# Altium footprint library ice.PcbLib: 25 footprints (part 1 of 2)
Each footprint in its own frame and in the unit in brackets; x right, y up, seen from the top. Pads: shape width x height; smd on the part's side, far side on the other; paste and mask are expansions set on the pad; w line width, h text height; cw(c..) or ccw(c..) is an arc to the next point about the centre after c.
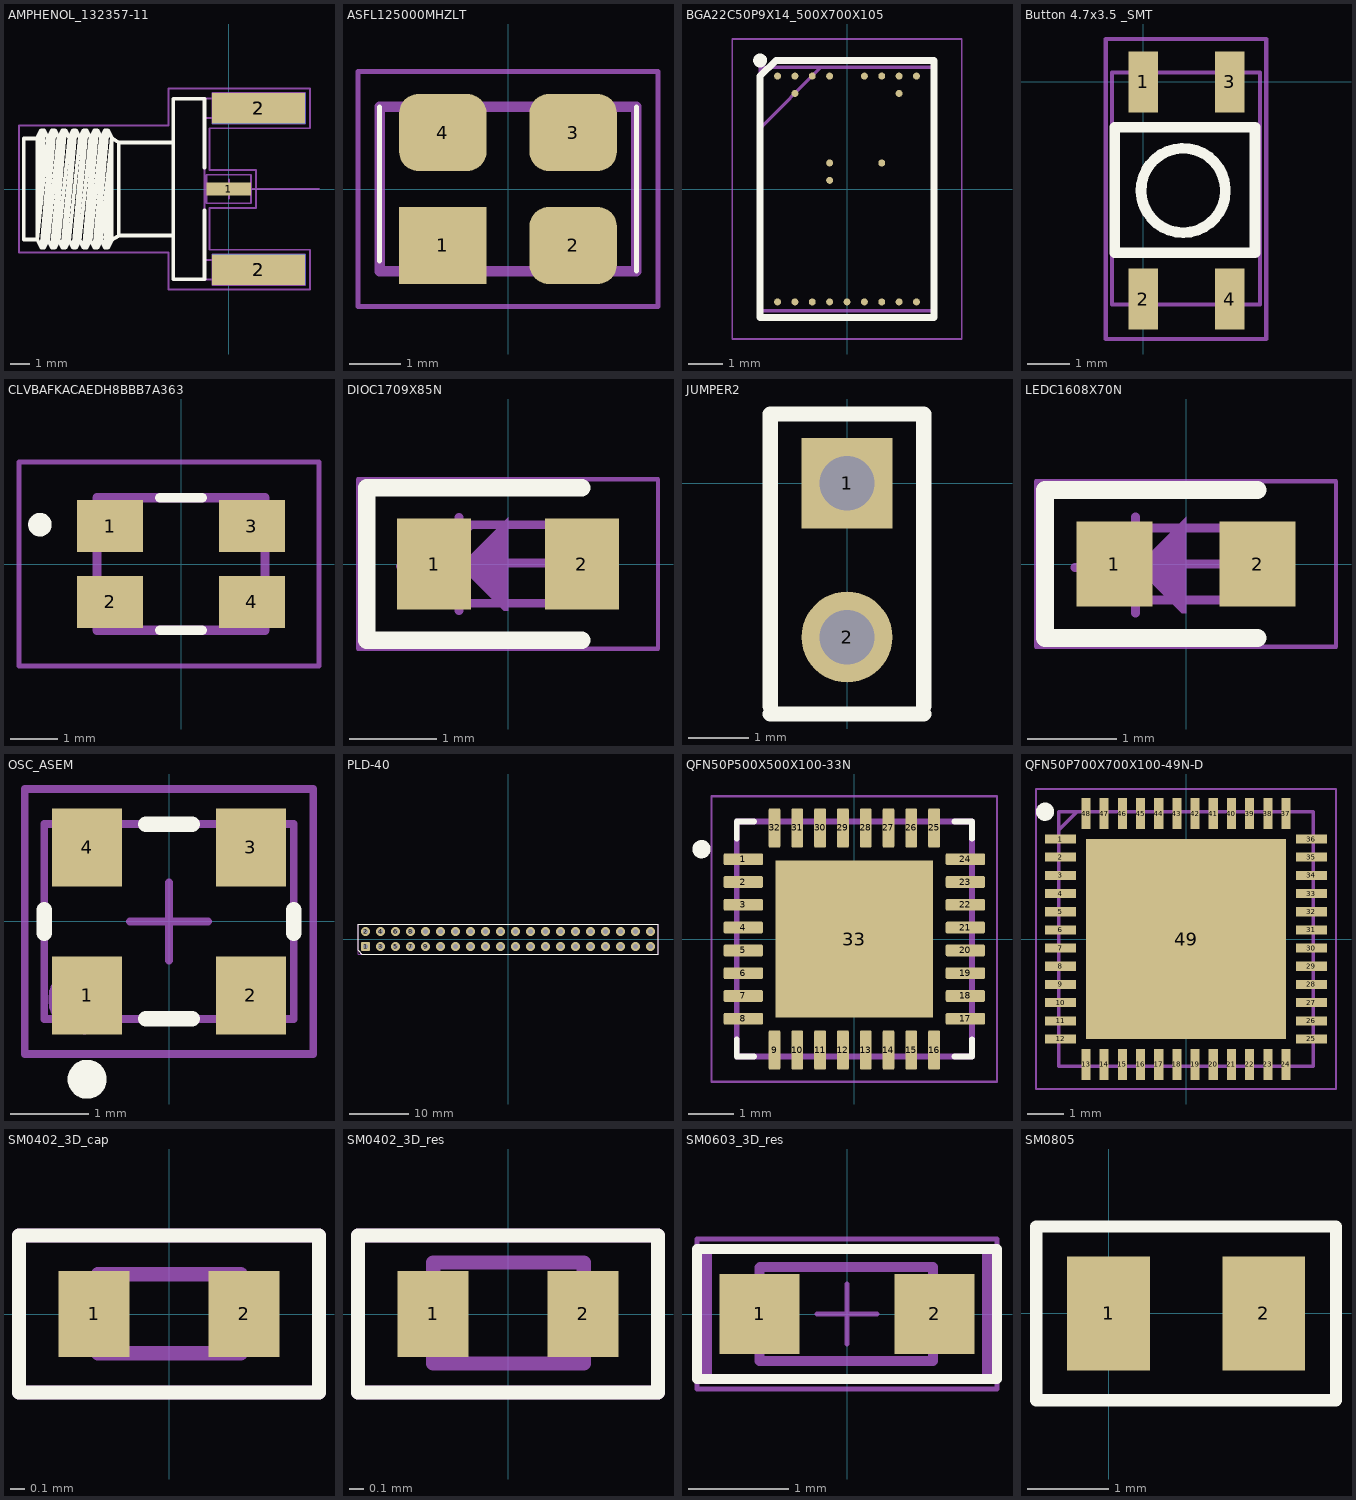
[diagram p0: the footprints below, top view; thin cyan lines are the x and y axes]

## AMPHENOL_132357-11 [mm]
height 1.2
pads (5):
  rect 2.35x0.7 smd: 1(0,0)
  rect 4.9x1.6 smd: 2(1.575,-4.25) 2(1.575,4.25)
  rect 4.9x1.6 smd far side: 2(1.575,-4.25) 2(1.575,4.25)
Top Overlay:
  lines w0.2: -10.09,2.665 -10.805,2.665 -10.805,-2.665 -10.09,-2.665 ; -6.17,-2.665 -5.795,-2.453 ; -2.925,-2.453 -5.795,-2.453 ; -2.925,2.447 -5.795,2.447 ; -1.275,-1.137 -1.275,-4.76 -2.925,-4.76 -2.925,4.76 -1.275,4.76 -1.275,1.137 ; -10.09,-2.665 -10.09,2.715 -9.879,3.094 ; -10.09,-2.665 -9.879,-3.094 ; -10.09,-2.665 -9.53,2.715 ; -10.09,-2.665 -9.741,3.094 ; -10.09,-2.665 -9.879,3.094 ; -9.879,-3.094 -9.741,-3.094 ; -9.879,-3.094 -9.319,3.094 ; -9.879,3.094 -9.741,3.094 ; -9.741,-3.094 -9.53,-2.715 ; -9.741,-3.094 -9.181,3.094 ; -9.741,3.094 -9.53,2.715 ; -9.53,-2.715 -9.319,-3.094 ; -9.53,-2.715 -8.97,2.715 ; -9.53,2.715 -9.319,3.094 ; -9.319,-3.094 -9.181,-3.094 ; -9.319,-3.094 -8.759,3.094 ; -9.319,3.094 -9.181,3.094 ; -9.181,-3.094 -8.97,-2.715 ; -9.181,-3.094 -8.621,3.094 ; -9.181,3.094 -8.97,2.715 ; -8.97,-2.715 -8.759,-3.094 ; -8.97,-2.715 -8.41,2.715 ; -8.97,2.715 -8.759,3.094 ; -8.759,-3.094 -8.621,-3.094 ; -8.759,-3.094 -8.199,3.094 ; -8.759,3.094 -8.621,3.094 ; -8.621,-3.094 -8.41,-2.715 ; -8.621,-3.094 -8.061,3.094 ; -8.621,3.094 -8.41,2.715 ; -8.41,-2.715 -8.199,-3.094 ; -8.41,-2.715 -7.85,2.715 ; -8.41,2.715 -8.199,3.094 ; -8.199,-3.094 -8.061,-3.094 ; -8.199,-3.094 -7.639,3.094 ; -8.199,3.094 -8.061,3.094 ; -8.061,-3.094 -7.85,-2.715 ; -8.061,-3.094 -7.501,3.094 ; -8.061,3.094 -7.85,2.715 ; -7.85,-2.715 -7.639,-3.094 ; -7.85,-2.715 -7.29,2.715 ; -7.85,2.715 -7.639,3.094 ; -7.639,-3.094 -7.501,-3.094 ; -7.639,-3.094 -7.079,3.094 ; -7.639,3.094 -7.501,3.094 ; -7.501,-3.094 -7.29,-2.715 ; -7.501,-3.094 -6.941,3.094 ; -7.501,3.094 -7.29,2.715 ; -7.29,-2.715 -7.079,-3.094 ; -7.29,-2.715 -6.73,2.715 ; -7.29,2.715 -7.079,3.094 ; -7.079,-3.094 -6.941,-3.094 ; -7.079,-3.094 -6.519,3.094 ; -7.079,3.094 -6.941,3.094 ; -6.941,-3.094 -6.73,-2.715 ; -6.941,-3.094 -6.381,3.094 ; -6.941,3.094 -6.73,2.715 ; -6.73,-2.715 -6.519,-3.094 ; -6.73,-2.715 -6.17,2.713 ; -6.73,2.715 -6.519,3.094 ; -6.519,-3.094 -6.381,-3.094 ; -6.519,-3.094 -6.17,2.713 ; -6.519,3.094 -6.381,3.094 ; -6.381,-3.094 -6.17,-2.715 -6.17,2.713 ; -6.381,-3.094 -6.17,2.665 -5.795,2.447 ; -6.381,3.094 -6.17,2.713 ; -5.795,-2.453 -5.795,2.447
Mechanical 8:
  lines w0.1: -0.5,0 0,0 ; 0,-0.5 0,0 ; 0,0.5 0,0 ; 0.5,0 0,0 ; 1.075,-4.25 1.575,-4.25 ; 1.075,4.25 1.575,4.25 ; 1.575,-4.75 1.575,-4.25 ; 1.575,-3.75 1.575,-4.25 ; 1.575,3.75 1.575,4.25 ; 1.575,4.75 1.575,4.25 ; 2.075,-4.25 1.575,-4.25 ; 2.075,4.25 1.575,4.25 ; -1.175,-0.75 -1.175,0.75 1.175,0.75 1.175,-0.75 -1.175,-0.75 ; -0.875,-5.05 4.025,-5.05 4.025,-3.45 -0.875,-3.45 -0.875,-5.05 ; -0.875,3.45 4.025,3.45 4.025,5.05 -0.875,5.05 -0.875,3.45
Mechanical 14:
  lines w0.1: -10.09,2.665 -10.805,2.665 -10.805,-2.665 -10.09,-2.665 ; -6.17,-2.665 -5.795,-2.453 ; -2.925,-2.453 -5.795,-2.453 ; -2.925,2.447 -5.795,2.447 ; -1.275,-4.76 -1.275,0 ; -1.275,-3.74 3.475,-3.74 3.475,-4.76 -2.925,-4.76 -2.925,4.76 3.475,4.76 3.475,3.74 -1.275,3.74 ; -1.275,-0.251 0.635,-0.251 0.635,0.251 -1.275,0.251 ; -1.275,4.76 -1.275,0 ; 4.75,0 -1.275,0 ; -10.09,-2.665 -10.09,2.715 -9.879,3.094 ; -10.09,-2.665 -9.879,-3.094 ; -10.09,-2.665 -9.53,2.715 ; -10.09,-2.665 -9.741,3.094 ; -10.09,-2.665 -9.879,3.094 ; -9.879,-3.094 -9.741,-3.094 ; -9.879,-3.094 -9.319,3.094 ; -9.879,3.094 -9.741,3.094 ; -9.741,-3.094 -9.53,-2.715 ; -9.741,-3.094 -9.181,3.094 ; -9.741,3.094 -9.53,2.715 ; -9.53,-2.715 -9.319,-3.094 ; -9.53,-2.715 -8.97,2.715 ; -9.53,2.715 -9.319,3.094 ; -9.319,-3.094 -9.181,-3.094 ; -9.319,-3.094 -8.759,3.094 ; -9.319,3.094 -9.181,3.094 ; -9.181,-3.094 -8.97,-2.715 ; -9.181,-3.094 -8.621,3.094 ; -9.181,3.094 -8.97,2.715 ; -8.97,-2.715 -8.759,-3.094 ; -8.97,-2.715 -8.41,2.715 ; -8.97,2.715 -8.759,3.094 ; -8.759,-3.094 -8.621,-3.094 ; -8.759,-3.094 -8.199,3.094 ; -8.759,3.094 -8.621,3.094 ; -8.621,-3.094 -8.41,-2.715 ; -8.621,-3.094 -8.061,3.094 ; -8.621,3.094 -8.41,2.715 ; -8.41,-2.715 -8.199,-3.094 ; -8.41,-2.715 -7.85,2.715 ; -8.41,2.715 -8.199,3.094 ; -8.199,-3.094 -8.061,-3.094 ; -8.199,-3.094 -7.639,3.094 ; -8.199,3.094 -8.061,3.094 ; -8.061,-3.094 -7.85,-2.715 ; -8.061,-3.094 -7.501,3.094 ; -8.061,3.094 -7.85,2.715 ; -7.85,-2.715 -7.639,-3.094 ; -7.85,-2.715 -7.29,2.715 ; -7.85,2.715 -7.639,3.094 ; -7.639,-3.094 -7.501,-3.094 ; -7.639,-3.094 -7.079,3.094 ; -7.639,3.094 -7.501,3.094 ; -7.501,-3.094 -7.29,-2.715 ; -7.501,-3.094 -6.941,3.094 ; -7.501,3.094 -7.29,2.715 ; -7.29,-2.715 -7.079,-3.094 ; -7.29,-2.715 -6.73,2.715 ; -7.29,2.715 -7.079,3.094 ; -7.079,-3.094 -6.941,-3.094 ; -7.079,-3.094 -6.519,3.094 ; -7.079,3.094 -6.941,3.094 ; -6.941,-3.094 -6.73,-2.715 ; -6.941,-3.094 -6.381,3.094 ; -6.941,3.094 -6.73,2.715 ; -6.73,-2.715 -6.519,-3.094 ; -6.73,-2.715 -6.17,2.713 ; -6.73,2.715 -6.519,3.094 ; -6.519,-3.094 -6.381,-3.094 ; -6.519,-3.094 -6.17,2.713 ; -6.519,3.094 -6.381,3.094 ; -6.381,-3.094 -6.17,-2.715 -6.17,2.713 ; -6.381,-3.094 -6.17,2.665 -5.795,2.447 ; -6.381,3.094 -6.17,2.713 ; -5.795,-2.453 -5.795,2.447
Top Assembly:
  lines w0.1: -11.055,-3.344 -3.175,-3.344 -3.175,-5.3 4.275,-5.3 4.275,-3.2 -1.025,-3.2 -1.025,-1 1.425,-1 1.425,1 -1.025,1 -1.025,3.2 4.275,3.2 4.275,5.3 -3.175,5.3 -3.175,3.344 -11.055,3.344 -11.055,-3.344
3D body "AMPHENOL_132357-11.stp": height 4.08, standoff -3.84, extent -10.805,-4.76 3.475,4.76

## ASFL125000MHZLT [mm]
height 1.2
pads (4):
  rect 1.7x1.5 smd: 1(-1.27,-1.1)
  rrect50% 1.7x1.5 smd: 2(1.27,-1.1) 3(1.27,1.1) 4(-1.27,1.1)
Top Overlay:
  lines w0.1: -2.5,-1.4 -2.5,1.6 ; 2.5,-1.6 2.5,1.6
M13_3D_Outline:
  lines w0.2: -2.5,-1.6 2.5,-1.6 2.5,1.6 -2.5,1.6 -2.5,-1.6
Top Assembly:
  lines w0.1: -2.921,-2.286 2.921,-2.286 ; -2.921,-2.286 -2.921,2.286 ; -2.921,-2.286 2.921,-2.286 ; -2.921,-2.286 -2.921,2.286 ; -2.921,2.286 2.921,2.286 ; -2.921,2.286 2.921,2.286 ; 2.921,-2.286 2.921,2.286 ; 2.921,-2.286 2.921,2.286
  text ".Designator" at -0.078,-0.092 h0.7
3D body "ASFL1-25.000MHZ-L-T.stp": height 1.4, standoff 0, extent -2.5,-1.7 2.5,1.7

## BGA22C50P9X14_500X700X105 [mm]
height 1.2
pads (22):
  round 0.2 smd: A1(-2,3.25) A2(-1.5,3.25) A3(-1,3.25) A4(-0.5,3.25) A6(0.5,3.25) A7(1,3.25) A8(1.5,3.25) A9(2,3.25) B2(-1.5,2.75) B8(1.5,2.75) F4(-0.5,0.75) F7(1,0.75) G4(-0.5,0.25) P1(-2,-3.25) P2(-1.5,-3.25) P3(-1,-3.25) P4(-0.5,-3.25) P5(0,-3.25) P6(0.5,-3.25) P7(1,-3.25) P8(1.5,-3.25) P9(2,-3.25)
Top Overlay:
  circle w0.2: c-2.5,3.7 r0.1
  lines w0.2: -2.5,-3.7 -2.5,3.25 -2.05,3.7 2.5,3.7 2.5,-3.7 -2.5,-3.7
Top Courtyard:
  lines w0.05: -3.302,-4.318 -3.302,4.318 3.302,4.318 3.302,-4.318 -3.302,-4.318
M13_3D_Outline:
  lines w0.1: -2.5,1.75 -0.75,3.5 ; -2.5,-3.5 -2.5,3.5 2.5,3.5 2.5,-3.5 -2.5,-3.5
Top Assembly:
  lines w0.05: -3.302,-4.318 -3.302,4.318 3.302,4.318 3.302,-4.318 -3.302,-4.318
  text ".Designator" at -0.078,-0.092 h0.7
3D body "HV7361GA-G.stp": height 1.05, standoff 0, extent -2.5,-3.5 2.5,3.5

## Button 4.7x3.5 _SMT [mm] "EVQ-P9P02M_SMT"
height 2.1
pads (4):
  rect 0.7x1.45 smd: 1(0,0) 2(0,-5.15) 3(2.05,0) 4(2.05,-5.15)
Top Overlay:
  lines w0.254: 1.949,-2.522 ccw(c0.95,-2.575) 1.95,-2.593 ; -0.675,-4.05 -0.675,-1.075 2.65,-1.075 2.65,-4.05 -0.675,-4.05
Top Courtyard:
  lines w0.1: -0.889,-6.096 2.921,-6.096 2.921,1.016 -0.889,1.016 -0.889,-6.096
M13_3D_Outline:
  lines w0.1: -0.735,-5.277 -0.735,0.225 2.773,0.225 2.773,-5.277 -0.735,-5.277
Top Assembly:
  lines w0.1: -0.889,-6.096 2.921,-6.096 2.921,1.016 -0.889,1.016 -0.889,-6.096
  text ".Designator" at 0.938,-2.759 h0.7
3D body "EVQ-P2-0246-02M+P9-HP-02M.stp": height 2.11, standoff 0.01, extent -0.719,-5.296 2.781,0.204

## CLVBAFKACAEDH8BBB7A363 [mm]
height 1.2
pads (4):
  rect 1.4x1.1 smd: 1(-1.5,0.8) 2(-1.5,-0.8) 3(1.5,0.8) 4(1.5,-0.8)
Top Overlay:
  circle w0.25: c-2.986,0.833 r0.125
  lines w0.2: -0.451,-1.4 0.451,-1.4 ; -0.451,1.4 0.451,1.4
Top Courtyard:
  lines w0.1: -3.429,-2.159 -3.429,2.159 2.921,2.159 2.921,-2.159 -3.429,-2.159
M13_3D_Outline:
  lines w0.2: -1.778,-1.4 1.778,-1.4 1.778,1.4 -1.778,1.4 -1.778,-1.4
Top Assembly:
  lines w0.1: -3.429,-2.159 2.921,-2.159 2.921,2.159 -3.429,2.159 -3.429,-2.159
  text ".Designator" at -0.078,-0.092 h0.7
3D body "CLVBA-FKA-CAEDH8BBB7A363--3DModel-STEP-56544.STEP": height 2.06, standoff -0.04, extent -1.75,-1.4 1.75,1.4

## DIOC1709X85N [mm]
height 1.2
pads (2):
  rect 0.85x1.05 smd: 1(-0.85,0) 2(0.85,0)
Top Overlay:
  lines w0.2: 0.85,-0.875 -1.625,-0.875 -1.625,0.875 0.85,0.875
Top Courtyard:
  lines w0.05: -1.725,-0.975 -1.725,0.975 1.725,0.975 1.725,-0.975 -1.725,-0.975
M13_3D_Outline:
  lines w0.1: -0.85,0.025 -0.425,0.45 ; -0.85,-0.45 -0.85,0.45 0.85,0.45 0.85,-0.45 -0.85,-0.45
Top Assembly:
  region: 0,0.538 -0.563,-0.025 -0.05,-0.537 0,-0.537
  lines w0.05: -1.725,-0.975 -1.725,0.975 1.725,0.975 1.725,-0.975 -1.725,-0.975
  lines w0.1: -1.237,-0.025 -0.563,-0.025 ; -0.563,-0.537 -0.563,0.538 ; 0,0.013 0.725,0.013
  text ".Designator" at -0.078,-0.092 h0.7
3D body "CDBU0520.stp": height 0.85, standoff 0, extent -0.85,-0.45 0.85,0.45

## JUMPER2 [mm]
pads (2):
  rect 1.5x1.5 hole 0.9: 1(0,0)
  round 1.5 hole 0.9: 2(0,-2.54)
Top Overlay:
  lines w0.254: -1.27,-3.81 1.27,-3.81 ; -1.27,-3.683 -1.27,1.143 1.27,1.143 1.27,-3.683
Top Courtyard:
  lines w0.1: -1.27,-3.81 1.27,-3.81 1.27,1.143 -1.27,1.143 -1.27,-3.81
M13_3D_Outline:
  lines w0.1: -1.27,-3.81 -1.27,1.143 1.27,1.143 1.27,-3.81 -1.27,-3.81
Top Assembly:
  lines w0.1: -1.27,-3.81 -1.27,1.143 1.27,1.143 1.27,-3.81 -1.27,-3.81
  text ".Designator" at 0.023,-1.395 h0.7
3D body "TSW-101-07-F-D.stp": height 8.39, standoff -2.53, extent -1.27,-3.81 1.27,1.27

## LEDC1608X70N [mm]
height 1.2
pads (2):
  rect 0.85x0.95 smd: 1(-0.8,0) 2(0.8,0)
Top Overlay:
  lines w0.2: 0.8,-0.825 -1.575,-0.825 -1.575,0.825 0.8,0.825
Top Courtyard:
  lines w0.05: -1.675,-0.925 -1.675,0.925 1.675,0.925 1.675,-0.925 -1.675,-0.925
M13_3D_Outline:
  lines w0.1: -0.8,0.133 -0.533,0.4 ; -0.8,-0.4 0.8,-0.4 0.8,0.4 -0.8,0.4 -0.8,-0.4
Top Assembly:
  region: 0,0.525 -0.563,-0.038 -0.05,-0.55 0,-0.55
  lines w0.05: -1.675,-0.925 1.675,-0.925 1.675,0.925 -1.675,0.925 -1.675,-0.925
  lines w0.1: -1.237,-0.038 -0.563,-0.038 ; -0.563,-0.55 -0.563,0.525 ; 0,0 0.725,0
  text ".Designator" at -0.078,-0.104 h0.7
3D body "LED_SML-LX0603GW-TR_LUM.step": height 0.61, standoff 0, extent -0.8,-0.406 0.8,0.406

## OSC_ASEM [mm]
pads (4):
  rect 0.9x1 smd mask+0.051: 1(-1.05,-0.95) 2(1.05,-0.95) 3(1.05,0.95) 4(-1.05,0.95)
Top Overlay:
  circle w0.25: c-1.05,-2.025 r0.125
  lines w0.2: -1.6,-0.15 -1.6,0.15 ; -0.3,-1.25 0.3,-1.25 ; -0.3,1.25 0.3,1.25 ; 1.6,-0.15 1.6,0.15
Top 3D Body:
  lines w0.1: -1.6,-1.25 1.6,-1.25 1.6,1.25 -1.6,1.25 -1.6,-1.25
Top Courtyard:
  lines w0.1: -0.5,0 0.5,0 ; 0,-0.5 0,0.5 ; -1.85,-1.7 1.85,-1.7 1.85,1.7 -1.85,1.7 -1.85,-1.7
Top Assembly:
  circle w0.1: c-1.1,-1 r0.4
  lines w0.1: -1.85,-1.7 -1.85,1.7 1.85,1.7 1.85,-1.7 -1.85,-1.7
  text ".Designator" at -1.5,-0.2 h0.7
3D body "OSC_ASEM.STEP": height 0.85, standoff 0, extent -1.6,-1.25 1.6,1.25

## PLD-40 [mm]
height 1.2
pads (40):
  rrect30% 1.5x1.5 hole 0.9: 1(-24.13,-1.27)
  round 1.5 hole 0.9: 2(-24.13,1.27) 3(-21.59,-1.27) 4(-21.59,1.27) 5(-19.05,-1.27) 6(-19.05,1.27) 7(-16.51,-1.27) 8(-16.51,1.27) 9(-13.97,-1.27) 10(-13.97,1.27) 11(-11.43,-1.27) 12(-11.43,1.27) 13(-8.89,-1.27) 14(-8.89,1.27) 15(-6.35,-1.27) 16(-6.35,1.27) 17(-3.81,-1.27) 18(-3.81,1.27) 19(-1.27,-1.27) 20(-1.27,1.27) 21(1.27,-1.27) 22(1.27,1.27) 23(3.81,-1.27) 24(3.81,1.27) 25(6.35,-1.27) 26(6.35,1.27) 27(8.89,-1.27) 28(8.89,1.27) 29(11.43,-1.27) 30(11.43,1.27) 31(13.97,-1.27) 32(13.97,1.27) 33(16.51,-1.27) 34(16.51,1.27) 35(19.05,-1.27) 36(19.05,1.27) 37(21.59,-1.27) 38(21.59,1.27) 39(24.13,-1.27) 40(24.13,1.27)
Top Overlay:
  lines w0.2: -25.4,-1.905 -25.4,2.54 ; -25.4,-1.905 -24.765,-2.54 ; -25.4,-1.905 -25.4,2.54 ; -25.4,-1.905 -24.765,-2.54 ; -25.4,2.54 25.4,2.54 ; -25.4,2.54 25.4,2.54 ; -24.765,-2.54 25.4,-2.54 ; -24.765,-2.54 25.4,-2.54 ; 25.4,-2.54 25.4,2.54 ; 25.4,-2.54 25.4,2.54
Top Courtyard:
  lines w0.2: -25.4,-1.905 -25.4,2.54 25.4,2.54 25.4,-2.54 -24.765,-2.54 -25.4,-1.905
M13_3D_Outline:
  lines w0.2: -25.4,-2.54 -25.4,2.54 25.4,2.54 25.4,-2.54 -25.4,-2.54
Top Assembly:
  lines w0.2: -25.4,-1.905 -25.4,2.54 25.4,2.54 25.4,-2.54 -24.765,-2.54 -25.4,-1.905
  text ".Designator" at -0.235,-0.243 h1.5
3D body "TSW-120-07-F-D.stp": height 8.39, standoff -2.53, extent -25.4,-2.54 25.4,2.54

## QFN50P500X500X100-33N [mm]
pads (33):
  rrect25% 0.86x0.26 smd: 1(-2.435,1.75) 2(-2.435,1.25) 3(-2.435,0.75) 4(-2.435,0.25) 5(-2.435,-0.25) 6(-2.435,-0.75) 7(-2.435,-1.25) 8(-2.435,-1.75) 17(2.435,-1.75) 18(2.435,-1.25) 19(2.435,-0.75) 20(2.435,-0.25) 21(2.435,0.25) 22(2.435,0.75) 23(2.435,1.25) 24(2.435,1.75)
  rrect25% 0.26x0.86 smd: 9(-1.75,-2.435) 10(-1.25,-2.435) 11(-0.75,-2.435) 12(-0.25,-2.435) 13(0.25,-2.435) 14(0.75,-2.435) 15(1.25,-2.435) 16(1.75,-2.435) 25(1.75,2.435) 26(1.25,2.435) 27(0.75,2.435) 28(0.25,2.435) 29(-0.25,2.435) 30(-0.75,2.435) 31(-1.25,2.435) 32(-1.75,2.435)
  rect 3.45x3.45 smd paste-3: 33(0,0)
Top Overlay:
  circle w0.2: c-3.35,1.97 r0.1
  lines w0.127: -2.58,-2.2 -2.58,-2.58 -2.2,-2.58 ; -2.58,2.2 -2.58,2.58 -2.2,2.58 ; 2.2,-2.58 2.58,-2.58 2.58,-2.2 ; 2.2,2.58 2.58,2.58 2.58,2.2
Top Paste:
  region: 1.1,-1.105 -1.105,-1.105 -1.105,1.1 1.1,1.1
Top Courtyard:
  lines w0.05: -3.13,-3.13 -3.13,3.13 3.13,3.13 3.13,-3.13 -3.13,-3.13
M13_3D_Outline:
  lines w0.127: -2.58,-2.58 2.58,-2.58 2.58,2.58 -2.58,2.58 -2.58,-2.58
Top Assembly:
  lines w0.05: -3.13,-3.13 -3.13,3.13 3.13,3.13 3.13,-3.13 -3.13,-3.13
  text ".Designator" at -0.078,-0.092 h0.7
3D body "AD8332ACPZ-R2.STEP": height 0.88, standoff -0.02, extent -2.52,-2.52 2.52,2.52

## QFN50P700X700X100-49N-D [mm]
height 1.2
pads (49):
  rect 0.85x0.25 smd: 1(-3.45,2.75) 2(-3.45,2.25) 3(-3.45,1.75) 4(-3.45,1.25) 5(-3.45,0.75) 6(-3.45,0.25) 7(-3.45,-0.25) 8(-3.45,-0.75) 9(-3.45,-1.25) 10(-3.45,-1.75) 11(-3.45,-2.25) 12(-3.45,-2.75) 25(3.45,-2.75) 26(3.45,-2.25) 27(3.45,-1.75) 28(3.45,-1.25) 29(3.45,-0.75) 30(3.45,-0.25) 31(3.45,0.25) 32(3.45,0.75) 33(3.45,1.25) 34(3.45,1.75) 35(3.45,2.25) 36(3.45,2.75)
  rect 0.25x0.85 smd: 13(-2.75,-3.45) 14(-2.25,-3.45) 15(-1.75,-3.45) 16(-1.25,-3.45) 17(-0.75,-3.45) 18(-0.25,-3.45) 19(0.25,-3.45) 20(0.75,-3.45) 21(1.25,-3.45) 22(1.75,-3.45) 23(2.25,-3.45) 24(2.75,-3.45) 37(2.75,3.45) 38(2.25,3.45) 39(1.75,3.45) 40(1.25,3.45) 41(0.75,3.45) 42(0.25,3.45) 43(-0.25,3.45) 44(-0.75,3.45) 45(-1.25,3.45) 46(-1.75,3.45) 47(-2.25,3.45) 48(-2.75,3.45)
  rect 5.5x5.5 smd: 49(0,0)
Top Overlay:
  circle w0.25: c-3.875,3.5 r0.125
Top Courtyard:
  lines w0.05: -4.125,-4.125 4.125,-4.125 4.125,4.125 -4.125,4.125 -4.125,-4.125
M13_3D_Outline:
  lines w0.1: -3.5,3 -3,3.5 ; -3.5,-3.5 3.5,-3.5 3.5,3.5 -3.5,3.5 -3.5,-3.5
Top Assembly:
  lines w0.05: -4.125,-4.125 4.125,-4.125 4.125,4.125 -4.125,4.125 -4.125,-4.125
  text ".Designator" at -0.078,-0.092 h0.7
3D body "ICE40UP5K-SG48ITR.stp": height 1, standoff 0, extent -3.55,-3.55 3.55,3.55

## SM0402_3D_cap [mm] "0402 cap"
height 0.35
pads (2):
  rect 0.5x0.6 smd: 1(-0.525,0) 2(0.525,0)
Top Overlay:
  lines w0.1: -1.05,-0.55 -1.05,0.55 1.05,0.55 1.05,-0.55 -1.05,-0.55
Top Courtyard:
  lines w0.1: -1.05,-0.55 1.05,-0.55 1.05,0.55 -1.05,0.55 -1.05,-0.55
M13_3D_Outline:
  lines w0.1: -0.497,-0.274 -0.497,0.279 0.501,0.279 0.501,-0.274 -0.497,-0.274
Top Assembly:
  lines w0.1: -1.05,-0.55 1.05,-0.55 1.05,0.55 -1.05,0.55 -1.05,-0.55
  text ".Designator" at -0.078,-0.092 h0.7
3D body "CAP_0402.STEP": height 0.51, standoff 0.01, extent -0.5,-0.271 0.5,0.279

## SM0402_3D_res [mm] "0603 inch resistor"
height 0.35
pads (2):
  rect 0.5x0.6 smd: 1(-0.525,0) 2(0.525,0)
Top Overlay:
  lines w0.1: -1.05,-0.55 1.05,-0.55 1.05,0.55 -1.05,0.55 -1.05,-0.55
Top Courtyard:
  lines w0.1: -1.05,-0.55 -1.05,0.55 1.05,0.55 1.05,-0.55 -1.05,-0.55
M13_3D_Outline:
  lines w0.1: -0.523,-0.346 0.53,-0.346 0.53,0.361 -0.523,0.361 -0.523,-0.346
Top Assembly:
  lines w0.1: -1.05,-0.55 -1.05,0.55 1.05,0.55 1.05,-0.55 -1.05,-0.55
  text ".Designator" at -0.078,-0.092 h0.7
3D body "RES_0402N.step": height 0.51, standoff 0.01, extent -0.52,-0.349 0.53,0.362

## SM0603_3D_res [mm] "0603 inch resistor"
height 0.45
pads (2):
  rect 0.8x0.8 smd: 1(-0.875,0) 2(0.875,0)
Top Overlay:
  lines w0.1: -1.5,-0.65 -1.5,0.65 1.5,0.65 1.5,-0.65 -1.5,-0.65
Top Courtyard:
  lines w0.05: -1.5,-0.75 1.5,-0.75 1.5,0.75 -1.5,0.75 -1.5,-0.75
M13_3D_Outline:
  lines w0.1: -0.875,0.466 -0.875,-0.469 0.861,-0.469 0.861,0.472 -0.87,0.472
Mechanical 14:
  lines w0.1: -1.4,-0.65 -1.4,0.65 1.4,0.65 1.4,-0.65 -1.4,-0.65
Top Assembly:
  lines w0.05: -0.3,0 0.3,0 ; 0,-0.3 0,0.3 ; -1.5,-0.75 1.5,-0.75 1.5,0.75 -1.5,0.75 -1.5,-0.75
  text ".Designator" at -0.104,-0.125 h0.7
3D body "RESC1608X55N.stp": height 0.55, standoff 0, extent -0.875,-0.475 0.875,0.475

## SM0805 [mil]
height 47.24
pads (2):
  rect 40x55 smd: 1(0,0) 2(75,0)
Top Overlay:
  lines w5.91: -35,-42 -35,42 110,42 110,-42 -35,-42
Top Courtyard:
  lines w3.94: -35.09,-42.58 -35.09,41.95 110,41.95 110,-42.58 -35.09,-42.58
Top Assembly:
  lines w3.94: -35.09,-42.58 -35.09,41.95 110,41.95 110,-42.58 -35.09,-42.58
  text ".Designator" at 25.91,-4.91 h27.56
3D body "INDC2012X110N.stp": height 43.31, standoff 0, extent -3.3,-27.55 83.31,27.56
